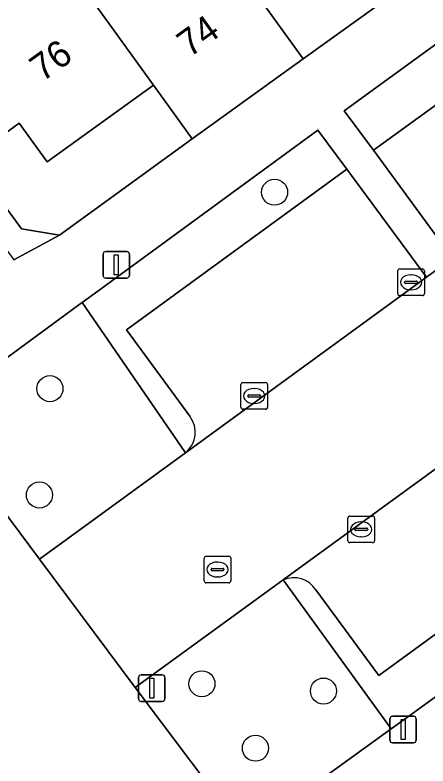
# Model space of a CAD drawing. Extents: x 159817 to 160765, y 380688 to 381638.
# Drawn here: x 159915.81 to 159931.31, y 381250 to 381278.22 of the extents above; entities that cross this region are included whole.
import ezdxf

# ---------------------------------------------------------------- set-up
doc = ezdxf.new("R2010")
doc.units = 0
for name, color, linetype in [('IMGEO_Boom', 7, 'Continuous'), ('IMGEO_Brandkraan', 7, 'Continuous'), ('IMGEO_Erf', 7, 'Continuous'), ('IMGEO_Groenvoorziening', 7, 'Continuous'), ('IMGEO_Haag', 7, 'Continuous'), ('IMGEO_Kolk', 7, 'Continuous'), ('IMGEO_Lichtmast', 7, 'Continuous'), ('IMGEO_Pand', 7, 'Continuous'), ('IMGEO_Pand_nummerreeks', 7, 'Continuous'), ('IMGEO_Parkeervlak_open', 7, 'Continuous'), ('IMGEO_Rijbaan_lokaal_open', 7, 'Continuous'), ('IMGEO_Verkeersbordpaal', 7, 'Continuous'), ('IMGEO_Voetpad_open', 7, 'Continuous')]:
    doc.layers.add(name, color=color, linetype=linetype)

msp = doc.modelspace()

# ---------------------------------------------------------------- linework, layer by layer
at = {"layer": 'IMGEO_Boom'}
for centre in [(159925.552, 381271.559), (159917.122, 381264.179), (159916.727, 381260.185), (159922.825, 381253.093), (159927.386, 381252.82), (159924.832, 381250.672)]:
    msp.add_circle(centre, 0.489, dxfattribs=at)
at = {"layer": 'IMGEO_Brandkraan'}
for p, q in [((159922.984, 381257.885), (159923.836, 381257.885)), ((159922.909, 381256.959), (159922.909, 381257.811)), ((159923.397, 381257.665), (159923.422, 381257.665)), ((159923.91, 381257.811), (159923.91, 381256.959)), ((159923.168, 381257.379), (159923.168, 381257.391)), ((159923.606, 381257.342), (159923.208, 381257.342)), ((159923.211, 381257.428), (159923.609, 381257.428)), ((159923.652, 381257.391), (159923.652, 381257.379)), ((159923.42, 381257.105), (159923.395, 381257.105)), ((159923.836, 381256.885), (159922.984, 381256.885))]:
    msp.add_line(p, q, dxfattribs=at)
for points in [[(159922.984, 381257.885), (159923.836, 381257.885)], [(159922.909, 381256.959), (159922.909, 381257.811)], [(159923.91, 381257.811), (159923.91, 381256.959)], [(159923.836, 381256.885), (159922.984, 381256.885)]]:
    msp.add_lwpolyline(points, dxfattribs=at)
for centre, radius, start, end in [((159922.986, 381257.809), 0.0765, 91.552, 178.448), ((159922.986, 381257.809), 0.0765, 91.552, 178.448), ((159923.834, 381257.809), 0.0765, 1.552, 88.448), ((159923.834, 381257.809), 0.0765, 1.552, 88.448), ((159923.208, 381257.388), 0.0403, 85.8775, 175.7526), ((159923.205, 381257.378), 0.0366, 178.938, 274.7102), ((159923.609, 381257.385), 0.043, 264.8664, 352.4533), ((159923.613, 381257.39), 0.0386, 1.7309, 96.639), ((159922.986, 381256.961), 0.0765, 181.552, 268.448), ((159922.986, 381256.961), 0.0765, 181.552, 268.448), ((159923.834, 381256.961), 0.0765, 271.552, 358.448), ((159923.834, 381256.961), 0.0765, 271.552, 358.448)]:
    msp.add_arc(centre, radius, start, end, dxfattribs=at)
for centre, major_axis, ratio, start_param, end_param in [((159923.396, 381257.385), (-0.387, 0.002), 0.722429, 4.712389, 7.853982), ((159923.421, 381257.385), (-0.39, 0.002), 0.717154, 1.570796, 4.712389)]:
    msp.add_ellipse(centre, major_axis=major_axis, ratio=ratio, start_param=start_param, end_param=end_param, dxfattribs=at)
at = {"layer": 'IMGEO_Erf'}
msp.add_lwpolyline([(159922.465, 381273.568), (159921.01, 381275.583), (159917.013, 381272.701), (159915.964, 381274.153), (159914.122, 381272.811), (159916.058, 381270.188), (159917.486, 381269.946)], close=True, dxfattribs=at)
at = {"layer": 'IMGEO_Groenvoorziening'}
for points in [[(159945.034, 381284.633), (159943.953, 381286.112), (159928.168, 381274.619), (159929.263, 381273.143), (159935.518, 381277.669), (159937.889, 381274.416)], [(159928.268, 381272.428), (159927.172, 381273.89), (159918.92, 381267.847), (159918.337, 381267.42), (159922.213, 381261.774)], [(159922.373, 381263.142), (159919.993, 381266.384), (159928.268, 381272.428)], [(159938.857, 381257.878), (159937.737, 381259.439), (159929.463, 381253.408), (159927.099, 381256.616)], [(159925.878, 381256.995), (159929.93, 381251.403), (159930.588, 381251.88), (159938.857, 381257.878)]]:
    msp.add_lwpolyline(points, dxfattribs=at)
for points in [[(159918.337, 381267.42), (159918.153, 381267.285), (159912.646, 381263.252), (159916.734, 381257.771), (159922.213, 381261.774)], [(159925.878, 381256.995), (159920.314, 381252.949), (159924.464, 381247.438), (159929.93, 381251.403)]]:
    msp.add_lwpolyline(points, close=True, dxfattribs=at)
for centre, radius, start, end in [((159921.576, 381262.542), 0.998, 309.6692, 36.9888), ((159926.274, 381256.116), 0.964, 31.239, 114.2722)]:
    msp.add_arc(centre, radius, start, end, dxfattribs=at)
at = {"layer": 'IMGEO_Haag'}
for points in [[(159939.211, 381274.16), (159939.322, 381274.241), (159936.378, 381278.301), (159945.034, 381284.633), (159943.953, 381286.112), (159928.168, 381274.619), (159929.263, 381273.143), (159935.518, 381277.669), (159937.889, 381274.416)], [(159928.268, 381272.428), (159927.172, 381273.89), (159918.92, 381267.847), (159918.337, 381267.42), (159922.213, 381261.774)], [(159922.373, 381263.142), (159919.993, 381266.384), (159928.268, 381272.428)], [(159938.857, 381257.878), (159937.737, 381259.439), (159929.463, 381253.408), (159927.099, 381256.616)], [(159925.878, 381256.995), (159929.93, 381251.403), (159930.588, 381251.88), (159938.857, 381257.878)]]:
    msp.add_lwpolyline(points, dxfattribs=at)
for centre, radius, start, end in [((159921.576, 381262.542), 0.998, 309.6692, 36.9888), ((159926.274, 381256.116), 0.964, 31.239, 114.2722)]:
    msp.add_arc(centre, radius, start, end, dxfattribs=at)
at = {"layer": 'IMGEO_Kolk'}
for p, q in [((159930.172, 381267.749), (159930.172, 381268.601)), ((159930.247, 381268.675), (159931.099, 381268.675)), ((159931.173, 381268.601), (159931.173, 381267.749)), ((159930.66, 381268.455), (159930.685, 381268.455)), ((159930.431, 381268.169), (159930.431, 381268.181)), ((159930.869, 381268.132), (159930.471, 381268.132)), ((159930.474, 381268.218), (159930.872, 381268.218)), ((159930.915, 381268.181), (159930.915, 381268.169)), ((159930.683, 381267.895), (159930.658, 381267.895)), ((159931.099, 381267.675), (159930.247, 381267.675)), ((159924.287, 381263.48), (159924.287, 381264.332)), ((159924.362, 381264.406), (159925.214, 381264.406)), ((159925.288, 381264.332), (159925.288, 381263.48)), ((159924.775, 381264.186), (159924.8, 381264.186)), ((159924.546, 381263.9), (159924.546, 381263.912)), ((159924.984, 381263.863), (159924.586, 381263.863)), ((159924.589, 381263.949), (159924.987, 381263.949)), ((159925.03, 381263.912), (159925.03, 381263.9)), ((159924.798, 381263.626), (159924.773, 381263.626)), ((159925.214, 381263.406), (159924.362, 381263.406)), ((159928.306, 381258.468), (159928.306, 381259.32)), ((159928.381, 381259.394), (159929.233, 381259.394)), ((159929.307, 381259.32), (159929.307, 381258.468)), ((159928.794, 381259.174), (159928.819, 381259.174)), ((159928.565, 381258.888), (159928.565, 381258.9)), ((159929.003, 381258.851), (159928.605, 381258.851)), ((159928.608, 381258.937), (159929.006, 381258.937)), ((159929.049, 381258.9), (159929.049, 381258.888)), ((159928.817, 381258.614), (159928.792, 381258.614)), ((159929.233, 381258.394), (159928.381, 381258.394))]:
    msp.add_line(p, q, dxfattribs=at)
for points in [[(159930.172, 381267.749), (159930.172, 381268.601)], [(159930.247, 381268.675), (159931.099, 381268.675)], [(159931.173, 381268.601), (159931.173, 381267.749)], [(159931.099, 381267.675), (159930.247, 381267.675)], [(159924.287, 381263.48), (159924.287, 381264.332)], [(159924.362, 381264.406), (159925.214, 381264.406)], [(159925.288, 381264.332), (159925.288, 381263.48)], [(159925.214, 381263.406), (159924.362, 381263.406)], [(159928.306, 381258.468), (159928.306, 381259.32)], [(159928.381, 381259.394), (159929.233, 381259.394)], [(159929.307, 381259.32), (159929.307, 381258.468)], [(159929.233, 381258.394), (159928.381, 381258.394)]]:
    msp.add_lwpolyline(points, dxfattribs=at)
for centre, radius, start, end in [((159930.249, 381268.599), 0.0765, 91.552, 178.448), ((159930.249, 381268.599), 0.0765, 91.552, 178.448), ((159931.097, 381268.599), 0.0765, 1.552, 88.448), ((159931.097, 381268.599), 0.0765, 1.552, 88.448), ((159930.471, 381268.178), 0.0403, 85.8775, 175.7526), ((159930.468, 381268.168), 0.0366, 178.938, 274.7102), ((159930.872, 381268.175), 0.043, 264.8664, 352.4533), ((159930.876, 381268.18), 0.0386, 1.7309, 96.639), ((159930.249, 381267.751), 0.0765, 181.552, 268.448), ((159930.249, 381267.751), 0.0765, 181.552, 268.448), ((159931.097, 381267.751), 0.0765, 271.552, 358.448), ((159931.097, 381267.751), 0.0765, 271.552, 358.448), ((159924.364, 381264.33), 0.0765, 91.552, 178.448), ((159924.364, 381264.33), 0.0765, 91.552, 178.448), ((159925.212, 381264.33), 0.0765, 1.552, 88.448), ((159925.212, 381264.33), 0.0765, 1.552, 88.448), ((159924.586, 381263.909), 0.0403, 85.8775, 175.7526), ((159924.583, 381263.899), 0.0366, 178.938, 274.7102), ((159924.987, 381263.906), 0.043, 264.8664, 352.4533), ((159924.991, 381263.911), 0.0386, 1.7309, 96.639), ((159924.364, 381263.482), 0.0765, 181.552, 268.448), ((159924.364, 381263.482), 0.0765, 181.552, 268.448), ((159925.212, 381263.482), 0.0765, 271.552, 358.448), ((159925.212, 381263.482), 0.0765, 271.552, 358.448), ((159928.383, 381259.318), 0.0765, 91.552, 178.448), ((159928.383, 381259.318), 0.0765, 91.552, 178.448), ((159929.231, 381259.318), 0.0765, 1.552, 88.448), ((159929.231, 381259.318), 0.0765, 1.552, 88.448), ((159928.605, 381258.897), 0.0403, 85.8775, 175.7526), ((159928.602, 381258.887), 0.0366, 178.938, 274.7102), ((159929.006, 381258.894), 0.043, 264.8664, 352.4533), ((159929.01, 381258.899), 0.0386, 1.7309, 96.639), ((159928.383, 381258.47), 0.0765, 181.552, 268.448), ((159928.383, 381258.47), 0.0765, 181.552, 268.448), ((159929.231, 381258.47), 0.0765, 271.552, 358.448), ((159929.231, 381258.47), 0.0765, 271.552, 358.448)]:
    msp.add_arc(centre, radius, start, end, dxfattribs=at)
for centre, major_axis, ratio, start_param, end_param in [((159930.659, 381268.175), (-0.387, 0.002), 0.722429, 4.712389, 7.853982), ((159930.684, 381268.175), (-0.39, 0.002), 0.717154, 1.570796, 4.712389), ((159924.774, 381263.906), (-0.387, 0.002), 0.722429, 4.712389, 7.853982), ((159924.799, 381263.906), (-0.39, 0.002), 0.717154, 1.570796, 4.712389), ((159928.793, 381258.894), (-0.387, 0.002), 0.722429, 4.712389, 7.853982), ((159928.818, 381258.894), (-0.39, 0.002), 0.717154, 1.570796, 4.712389)]:
    msp.add_ellipse(centre, major_axis=major_axis, ratio=ratio, start_param=start_param, end_param=end_param, dxfattribs=at)
at = {"layer": 'IMGEO_Lichtmast'}
for p, q in [((159919.114, 381268.433), (159919.114, 381269.233)), ((159919.114, 381269.233), (159919.114, 381268.433)), ((159919.214, 381269.333), (159920.004, 381269.333)), ((159920.004, 381269.333), (159919.214, 381269.333)), ((159920.104, 381269.233), (159920.104, 381268.433)), ((159920.104, 381268.433), (159920.104, 381269.233)), ((159920.004, 381268.333), (159919.214, 381268.333)), ((159919.214, 381268.333), (159920.004, 381268.333)), ((159929.877, 381250.973), (159929.877, 381251.773)), ((159929.877, 381251.773), (159929.877, 381250.973)), ((159929.977, 381251.873), (159930.767, 381251.873)), ((159930.767, 381251.873), (159929.977, 381251.873)), ((159930.867, 381251.773), (159930.867, 381250.973)), ((159930.867, 381250.973), (159930.867, 381251.773)), ((159930.767, 381250.873), (159929.977, 381250.873)), ((159929.977, 381250.873), (159930.767, 381250.873))]:
    msp.add_line(p, q, dxfattribs=at)
for points in [[(159919.534, 381269.208), (159919.684, 381269.208), (159919.684, 381268.458), (159919.534, 381268.458), (159919.534, 381269.208)], [(159930.297, 381251.748), (159930.447, 381251.748), (159930.447, 381250.998), (159930.297, 381250.998), (159930.297, 381251.748)]]:
    msp.add_lwpolyline(points, dxfattribs=at)
for centre, start, end in [((159919.214, 381269.233), 90, 180), ((159919.214, 381269.233), 90, 180), ((159920.004, 381269.233), 0, 90), ((159920.004, 381269.233), 360, 90), ((159919.214, 381268.433), 180, 270), ((159919.214, 381268.433), 180, 270), ((159920.004, 381268.433), 270, 0), ((159920.004, 381268.433), 270, 0), ((159929.977, 381251.773), 90, 180), ((159929.977, 381251.773), 90, 180), ((159930.767, 381251.773), 0, 90), ((159930.767, 381251.773), 360, 90), ((159929.977, 381250.973), 180, 270), ((159929.977, 381250.973), 180, 270), ((159930.767, 381250.973), 270, 0), ((159930.767, 381250.973), 270, 0)]:
    msp.add_arc(centre, 0.1, start, end, dxfattribs=at)
at = {"layer": 'IMGEO_Pand'}
for points in [[(159916.396, 381282.185), (159914.19, 381285.509), (159910.973, 381290.04), (159908.186, 381288.26), (159911.58, 381283.599), (159908.11, 381281.06), (159914.122, 381272.811), (159915.964, 381274.153), (159917.013, 381272.701), (159921.01, 381275.583), (159916.606, 381281.692), (159916.701, 381281.761)], [(159919.032, 381287.091), (159926.625, 381276.57), (159930.688, 381279.502), (159926.309, 381285.569), (159924.528, 381288.036), (159922.359, 381286.472), (159920.928, 381288.458)], [(159916.396, 381282.185), (159916.701, 381281.761), (159916.606, 381281.692), (159921.01, 381275.583), (159922.465, 381273.568), (159926.625, 381276.57), (159919.032, 381287.091), (159917.186, 381285.76), (159918.612, 381283.782)]]:
    msp.add_lwpolyline(points, close=True, dxfattribs=at)
at = {"layer": 'IMGEO_Parkeervlak_open'}
for points in [[(159937.889, 381274.416), (159935.518, 381277.669), (159929.263, 381273.143), (159932.23, 381269.083), (159939.211, 381274.16)], [(159922.213, 381261.774), (159931.251, 381268.362), (159928.268, 381272.428), (159919.993, 381266.384), (159922.373, 381263.142)], [(159927.099, 381256.616), (159929.463, 381253.408), (159937.737, 381259.439), (159934.796, 381263.495), (159925.878, 381256.995)]]:
    msp.add_lwpolyline(points, dxfattribs=at)
for centre, radius, start, end in [((159921.576, 381262.542), 0.998, 309.6692, 36.9888), ((159926.274, 381256.116), 0.964, 31.239, 114.2722)]:
    msp.add_arc(centre, radius, start, end, dxfattribs=at)
at = {"layer": 'IMGEO_Rijbaan_lokaal_open'}
msp.add_lwpolyline([(159932.23, 381269.083), (159931.251, 381268.362), (159922.213, 381261.774), (159916.734, 381257.771), (159920.314, 381252.949), (159925.878, 381256.995), (159934.796, 381263.495), (159935.848, 381264.263), (159942.712, 381269.192), (159942.909, 381269.333), (159939.322, 381274.241), (159939.211, 381274.16)], close=True, dxfattribs=at)
at = {"layer": 'IMGEO_Verkeersbordpaal'}
for p, q in [((159920.447, 381252.53), (159920.447, 381253.33)), ((159920.447, 381253.33), (159920.447, 381252.53)), ((159920.547, 381253.43), (159921.337, 381253.43)), ((159921.337, 381253.43), (159920.547, 381253.43)), ((159921.437, 381253.33), (159921.437, 381252.53)), ((159921.437, 381252.53), (159921.437, 381253.33)), ((159921.337, 381252.43), (159920.547, 381252.43)), ((159920.547, 381252.43), (159921.337, 381252.43))]:
    msp.add_line(p, q, dxfattribs=at)
msp.add_lwpolyline([(159920.867, 381253.305), (159921.017, 381253.305), (159921.017, 381252.555), (159920.867, 381252.555), (159920.867, 381253.305)], dxfattribs=at)
for centre, start, end in [((159920.547, 381253.33), 90, 180), ((159920.547, 381253.33), 90, 180), ((159921.337, 381253.33), 0, 90), ((159921.337, 381253.33), 360, 90), ((159920.547, 381252.53), 180, 270), ((159920.547, 381252.53), 180, 270), ((159921.337, 381252.53), 270, 0), ((159921.337, 381252.53), 270, 0)]:
    msp.add_arc(centre, 0.1, start, end, dxfattribs=at)
at = {"layer": 'IMGEO_Voetpad_open'}
for points in [[(159912.646, 381263.252), (159918.153, 381267.285), (159918.337, 381267.42), (159918.92, 381267.847), (159927.172, 381273.89), (159928.268, 381272.428), (159931.251, 381268.362), (159932.23, 381269.083), (159929.263, 381273.143), (159928.168, 381274.619), (159943.953, 381286.112)], [(159974.309, 381283.732), (159957.647, 381271.588), (159955.676, 381270.159), (159939.851, 381258.605), (159938.747, 381260.139), (159935.848, 381264.263), (159934.796, 381263.495), (159937.737, 381259.439), (159938.857, 381257.878), (159930.588, 381251.88), (159929.93, 381251.403), (159924.464, 381247.438), (159925.634, 381244.77)], [(159930.688, 381279.502), (159926.625, 381276.57), (159922.465, 381273.568), (159917.486, 381269.946), (159915.771, 381269.023)], [(159916.734, 381257.771), (159912.646, 381263.252), (159910.976, 381265.571), (159909.52, 381264.523), (159907.762, 381266.819), (159906.736, 381268.158)], [(159925.634, 381244.77), (159924.464, 381247.438), (159920.314, 381252.949), (159916.734, 381257.771)]]:
    msp.add_lwpolyline(points, dxfattribs=at)
msp.add_lwpolyline([(159908.11, 381281.06), (159904.555, 381285.942), (159902.353, 381285.415), (159906.42, 381279.793), (159907.385, 381280.507), (159915.771, 381269.023), (159917.486, 381269.946), (159916.058, 381270.188), (159914.122, 381272.811)], close=True, dxfattribs=at)

# ---------------------------------------------------------------- texts
at = {"layer": 'IMGEO_Pand_nummerreeks'}
for s, rotation, p in [('74', 35.8169, (159922.359, 381276.599)), ('76', 35.8093, (159916.837, 381275.681))]:
    msp.add_text(s, height=1, rotation=rotation, dxfattribs=at).set_placement(p)

doc.saveas('drawing.dxf')
